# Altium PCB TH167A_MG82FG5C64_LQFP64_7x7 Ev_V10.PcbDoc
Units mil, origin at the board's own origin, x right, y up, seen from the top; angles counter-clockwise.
Board outline 3155 x 2110 mil, 2 copper layers (Top Layer, Bottom Layer); 56 components, 82 nets, 364 pads, 146 vias.
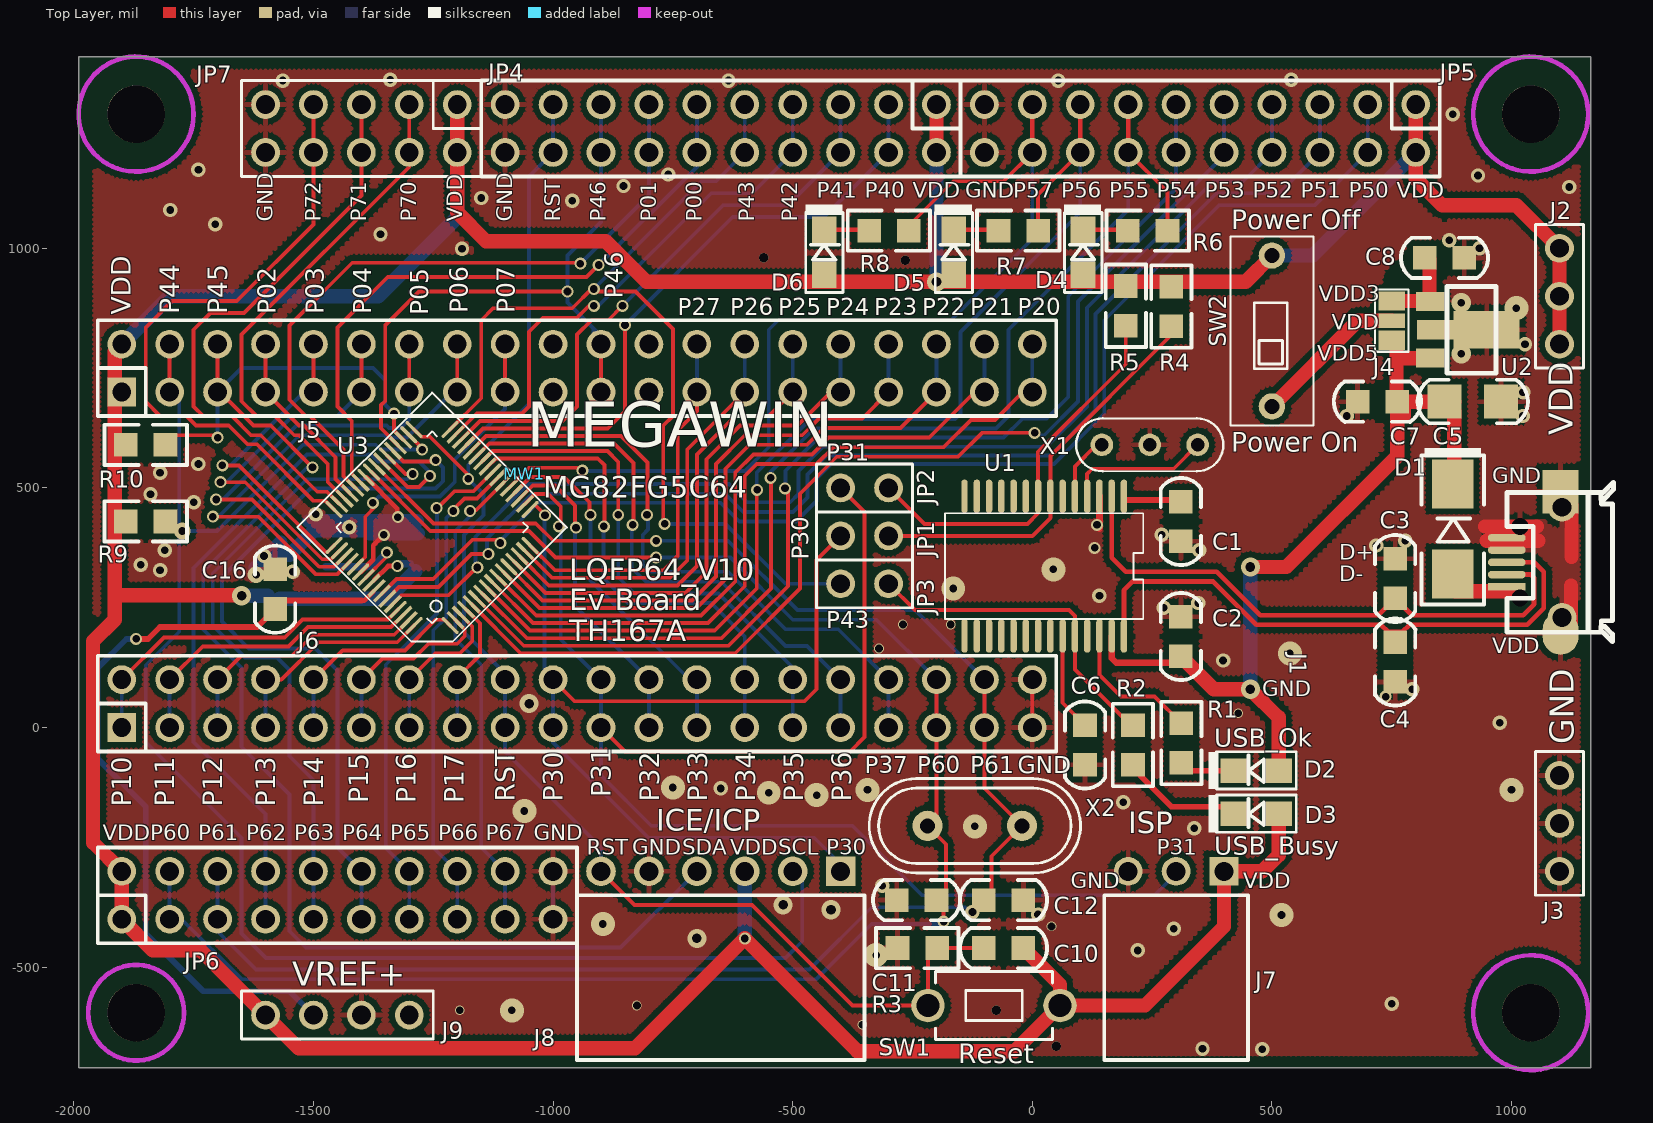
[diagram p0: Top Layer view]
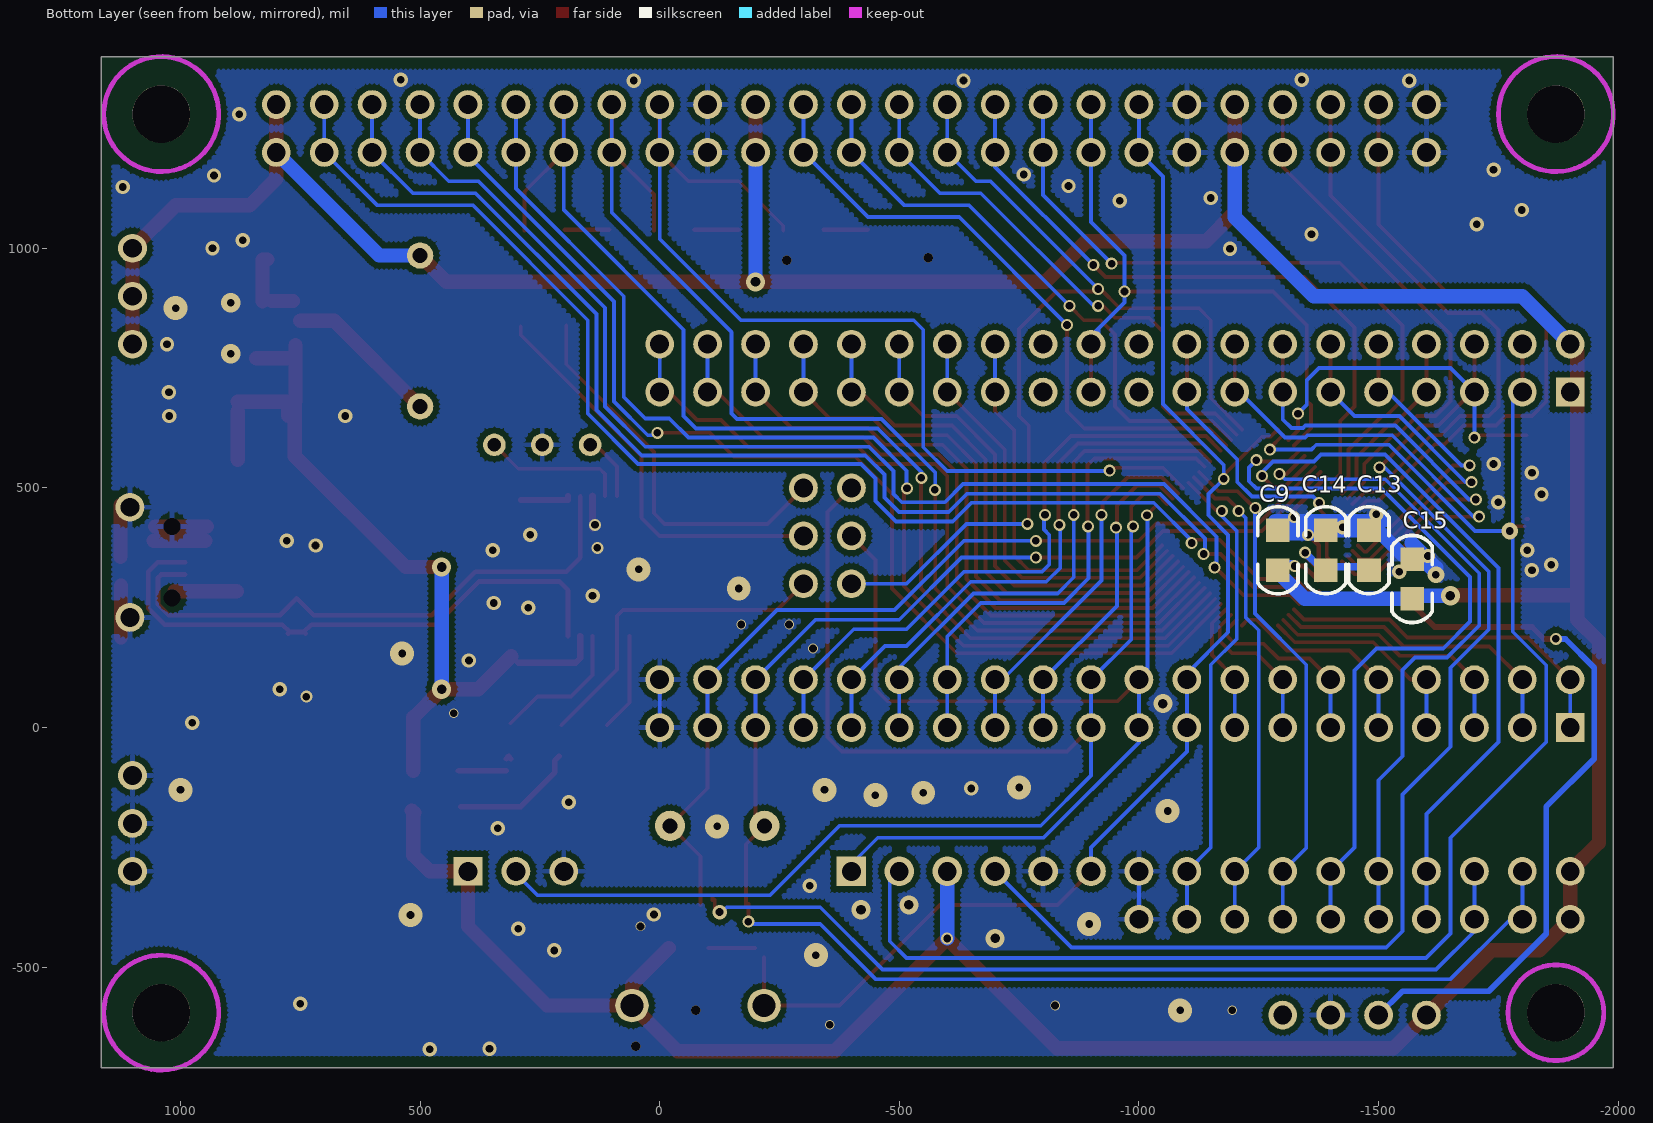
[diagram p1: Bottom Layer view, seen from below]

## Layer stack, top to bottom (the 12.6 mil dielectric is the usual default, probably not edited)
Top Layer: signal copper 1.4
Dielectric: dielectric 12.6, FR-4, Dk 4.8
Bottom Layer: signal copper 1.4

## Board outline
-1990,-710 -1990,1400 1165,1400 1165,-710

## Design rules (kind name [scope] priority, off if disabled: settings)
Clearance 12 [All] p1 off: gap=12
Clearance 10 [All] p2 off: gap=10
Clearance 6 [All] p3: gap=6
ComponentClearance [All] p1 off: gap=10 collisioncheckmode=3 verticalgap=10 showdistances=FALSE
HoleSize [All] p1: absolutevalues=TRUE maxlimit=500 minlimit=1 maxpercent=80.000 minpercent=20.000
MinimumSolderMaskSliver [All] p1 off: minsoldermaskwidth=10
PolygonConnect VIA [ISVIA] p1: connectstyle=Direct reliefconductorwidth=10 reliefentries=4 polygonreliefangle="90 Angle"
PolygonConnect [All] p2: connectstyle=Relief reliefconductorwidth=10 reliefentries=4 polygonreliefangle="90 Angle"
RoomDefinition TH167A_MG82FG5C64_LQFP64_V10 [InComponentClass('TH167A_MG82FG5C64_LQFP64_V10')] p1: confinementstyle=ConfineIn formatcopy=TRUE lockcomponents=FALSE outline -2265,-926 1350,-926 1350,1545 -2265,1545
RoutingVias [All] p1: holewidth=16 width=25 viastyle="Through Hole" minholewidth=16 minwidth=24 maxholewidth=28 maxwidth=50
SilkToSilkClearance [All] p1 off: silktosilkclearance=10
SilkscreenOverComponentPads [All] p1 off: minsilkscreentomaskgap=10
SolderMaskExpansion [All] p1 off: expansion=4
Width [All] p1: maxlimit=200 minlimit=6 preferedwidth=10
23 further rules are at their usual default settings.

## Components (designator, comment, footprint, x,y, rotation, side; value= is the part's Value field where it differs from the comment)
C1 "4.7uF" 0805C 310,430 r270 top
C2 "0.1uF" 0805C 310,190 r270 top
C3 "15pF" 0805C 757.2,310.79 r90 top
C4 "15pF" 0805C 757.2,136.62 r270 top
C5 "4.7uF" 1206C 919.06,680 r0 top
C6 "0.1uF" 0805C 110,-36.34 r90 top
C7 "0.1uF" 0805C 720,680 r180 top
C8 "4.7uF" 0805C 860,980 r0 top
C9 "0.1uF" 0805C -1290,370 r270 bottom
C10 "1u" 0805C -60,-460 r180 top
C11 "NC" 0805C -241.34,-360 r180 top
C12 "NC" 0805C -60,-360 r0 top
C13 "4.7uF" 0805C -1480,370 r90 bottom
C14 "0.1uF" 0805C -1390,370 r270 bottom
C15 "4.7uF" 0805C -1570,310 r90 bottom
C16 "0.1uF" 0805C -1580,288.66 r90 top
D1 "1N5817" D5817_SMD_1 877.2,414.45 r270 top
D2 "Yellow" 0805D 466.92,-90 r180 top
D3 "Red" 0805D 466.92,-180 r180 top
D4 "Green" 0805D 105.71,991.71 r90 top
D5 "Red" 0805D -164.29,991.71 r90 top
D6 "Green" 0805D -434.29,991.71 r90 top
J1 "Micro USB母座" JACK_USB_SMD290X220P065 990,344.72 r180 top
J2 "*" PS3P254 1100,800 r90 top
J3 "*" PS3P254 1100,-100 r270 top
J4 "*" JUMP3_SMD 750,849 r90 top
J5 "CON40A" PS20X2P254 -1900,700 r0 top locked
J6 "CON40A" PS20X2P254 -1900,0 r0 top
J7 "*" PS3P254f_90 400,-300 r180 top
J8 "*" PS6P254F_90 -400,-300 r180 top locked
J9 "CON4" PS4P254 -1600,-600 r0 top
JP1 "JUMPER2" PS2P254 -400,400 r0 top
JP2 "JUMPER2" PS2P254 -400,500 r0 top
JP3 "JUMPER2" PS2P254 -400,300 r0 top
JP4 "*" PS10X2P254 -200,1300 r180 top
JP5 "*" PS10X2P254 800,1300 r180 top
JP6 "*" PS10X2P254 -1900,-400 r0 top
JP7 "CON5X2" PS5X2P254 -1200,1300 r180 top
MW1 "MW-A4" MEGAWIN_T -1060,530 r0 top
R1 "1K" 0805R 311,-32.34 r270 top
R2 "1K" 0805R 210,-36.34 r270 top
R3 "47K" 0805R -240,-460 r0 top
R4 "4.7K" 0805R 290,878.66 r270 top
R5 "4.7K" 0805R 195,880 r270 top
R6 "1K" 0805R 240.71,1036.71 r180 top
R7 "1K" 0805R -29.29,1036.71 r180 top
R8 "1K" 0805R -299.29,1036.71 r180 top
R9 "4.7K" 0805R -1850,430 r180 top
R10 "4.7K" 0805R -1850,590 r180 top
SW1 "SW TACT-SPST" SW_T_2P -80,-580 r180 top
SW2 "-" DIP2_SW 500,670 r90 top
U1 "MA101_TSSOP28" SSOP28_220P065 24.84,336.85 r180 top
U2 "AIC1734-33(SOT-89)" SOT89 830,830 r270 top
U3 "MG82FG5C64" QFP64_7X7P040 -1252.42,417.62 r135 top locked (schematic designator U1)
X1 "6MHz" X3P 345,590 r180 top
X2 "NC" X49U -120,-205 r180 top

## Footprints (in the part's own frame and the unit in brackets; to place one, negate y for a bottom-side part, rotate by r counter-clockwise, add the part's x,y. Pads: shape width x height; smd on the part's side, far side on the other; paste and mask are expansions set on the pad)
0805C [mm]
  rect 1.25x1.25 smd: 1(-1.05,0) 2(1.05,0)
  silkscreen extent -2.31,-1.07 2.31,1.07
0805D [mm]
  rect 1.4x1.3 smd: 1(-1.192,0) 2(1.192,0)
  silkscreen extent -2.12,-1 2.53,0.98
0805R [mm]
  rect 1.25x1.25 smd: 1(-1.05,0) 2(1.05,0)
  silkscreen extent -2.18,-1.07 2.18,1.07
1206C [mm]
  rect 1.8x1.8 smd: 1(-1.5,0) 2(1.5,0)
  silkscreen extent -2.92,-1.15 2.92,1.16
D5817_SMD_1 [mm]
  rect 2.6x2.2 smd: 1(2.39,0) 2(-2.39,0)
  silkscreen extent -4.3,-1.65 4,1.65
DIP2_SW [mm]
  round 1.4 hole 0.8: 1(0,0) 2(8,0)
  silkscreen extent -1.02,-2.2 9.02,2.2
JACK_USB_SMD290X220P065 [mm]
  rect 1.9x1.8 on Mech2: 0(-2.85,-1.15) 0(-2.85,1.15)
  round 0.8 hole 0.9 unplated: 1(-0.7,1.9) 5(-0.7,-1.9)
  rect 2x0.4 smd: 1(0,1.3)
  oval 2x0.4 smd: 2(0,0.65) 3(0,0) 4(0,-0.65) 5(0,-1.3)
  round 1.524 hole 1: 5(-2.931,2.921) 5(-2.931,-2.921)
  oval 1.9x2.3 smd: 5(-2.85,3.75)
  rect 1.9x2.3 smd: 5(-2.85,-3.75)
  silkscreen extent -5.65,-4.25 -0.01,4.2
JUMP3_SMD [mil]
  rect 40x55 smd: 1(-41,0) 3(41,0)
  rect 30x55 smd: 2(0,0)
  silkscreen extent -65,-35 65,35
MEGAWIN_T [mil]
PS2P254 [mil]
  round 60 hole 39.37: 1(0,0) 2(100,0)
  silkscreen extent -50,-50 150,50
PS3P254 [mil]
  round 60 hole 39.37: 1(0,0) 2(100,0) 3(200,0)
  silkscreen extent -50,-50 250,50
PS3P254f_90 [mil]
  rect 60x60 hole 39.37: 1(0,0)
  round 60 hole 39.37: 2(100,0) 3(200,0)
  silkscreen extent -50,50 250,394
PS4P254 [mil]
  round 60 hole 39.37: 1(0,0) 2(100,0) 3(200,0) 4(300,0)
  silkscreen extent -50,-50 350,50
PS5X2P254 [mil]
  round 60 hole 39.37: 1(0,0) 2(0,100) 3(100,0) 4(100,100) 5(200,0) 6(200,100) 7(300,0) 8(300,100) 9(400,0) 10(400,100)
  silkscreen extent -50,-50 450,150
PS6P254F_90 [mil]
  rect 62x62 hole 39.37: 1(0,0)
  round 62 hole 39.37: 2(100,0) 3(200,0) 4(300,0) 5(400,0) 6(500,0)
  silkscreen extent -50,50 550,394
PS10X2P254 [mil]
  round 60 hole 39.37: 1(0,0) 2(0,100) 3(100,0) 4(100,100) 5(200,0) 6(200,100) 7(300,0) 8(300,100) 9(400,0) 10(400,100) 11(500,0) 12(500,100) 13(600,0) 14(600,100) 15(700,0) 16(700,100) 17(800,0) 18(800,100) 19(900,0) 20(900,100)
  silkscreen extent -50,-50 950,150
PS20X2P254 [mil]
  rect 60x60 hole 39.37: 1(0,0)
  round 60 hole 39.37: 2(0,100) 3(100,0) 4(100,100) 5(200,0) 6(200,100) 7(300,0) 8(300,100) 9(400,0) 10(400,100) 11(500,0) 12(500,100) 13(600,0) 14(600,100) 15(700,0) 16(700,100) 17(800,0) 18(800,100) 19(900,0) 20(900,100) 21(1000,0) 22(1000,100) 23(1100,0) 24(1100,100) 25(1200,0) 26(1200,100) 27(1300,0) 28(1300,100) 29(1400,0) 30(1400,100) 31(1500,0) 32(1500,100) 33(1600,0) 34(1600,100) 35(1700,0) 36(1700,100) 37(1800,0) 38(1800,100) 39(1900,0) 40(1900,100)
  silkscreen extent -50,-50 1950,150
QFP64_7X7P040 [mm]
  oval 1.2x0.19 smd: 1(-4.35,3) 12(-4.35,-1.4) 16(-4.35,-3) 33(4.35,-3) 34(4.35,-2.6) 38(4.35,-1) 41(4.35,0.2) 42(4.35,0.6) 48(4.35,3)
  rect 1.2x0.19 smd: 2(-4.35,2.6) 3(-4.35,2.2) 4(-4.35,1.8) 5(-4.35,1.4) 6(-4.35,1) 7(-4.35,0.6) 8(-4.35,0.2) 9(-4.35,-0.2) 10(-4.35,-0.6) 11(-4.35,-1) 13(-4.35,-1.8) 14(-4.35,-2.2) 15(-4.35,-2.6) 35(4.35,-2.2) 36(4.35,-1.8) 37(4.35,-1.4) 39(4.35,-0.6) 40(4.35,-0.2) 43(4.35,1) 44(4.35,1.4) 45(4.35,1.8) 46(4.35,2.2) 47(4.35,2.6)
  oval 0.19x1.2 smd: 17(-3,-4.35) 24(-0.2,-4.35) 27(1,-4.35) 32(3,-4.35) 49(3,4.35) 50(2.6,4.35) 53(1.4,4.35) 54(1,4.35) 61(-1.8,4.35) 64(-3,4.35)
  rect 0.19x1.2 smd: 18(-2.6,-4.35) 19(-2.2,-4.35) 20(-1.8,-4.35) 21(-1.4,-4.35) 22(-1,-4.35) 23(-0.6,-4.35) 25(0.2,-4.35) 26(0.6,-4.35) 28(1.4,-4.35) 29(1.8,-4.35) 30(2.2,-4.35) 31(2.6,-4.35) 51(2.2,4.35) 52(1.8,4.35) 55(0.6,4.35) 56(0.2,4.35) 57(-0.2,4.35) 58(-0.6,4.35) 59(-1,4.35) 60(-1.4,4.35) 62(-2.2,4.35) 63(-2.6,4.35)
  silkscreen extent -5.05,-5.05 5.05,5.05
SOT89 [mm]
  rect 1.016x1.5 smd: 1(-1.5,0) 3(1.5,0)
  rect 2x3.5 smd: 2(0,3)
  rect 1.016x2.6 smd: 2(0,0.6)
  silkscreen extent -2.3,0.9 2.3,3.5
SSOP28_220P065 [mil]
  oval 13.5x70 smd: 1(-166.34,-145.67) 2(-140.75,-145.67) 3(-115.16,-145.67) 4(-89.57,-145.67) 5(-63.98,-145.67) 6(-38.39,-145.67) 7(-12.79,-145.67) 8(12.8,-145.67) 9(38.39,-145.67) 10(63.98,-145.67) 11(89.57,-145.67) 12(115.16,-145.67) 13(140.75,-145.67) 14(166.34,-145.67) 15(166.34,145.67) 16(140.75,145.67) 17(115.16,145.67) 18(89.57,145.67) 19(63.98,145.67) 20(38.39,145.67) 21(12.8,145.67) 22(-12.79,145.67) 23(-38.39,145.67) 24(-63.98,145.67) 25(-89.57,145.67) 26(-115.16,145.67) 27(-140.75,145.67) 28(-166.34,145.67)
  silkscreen extent -207,-110 207,110
SW_T_2P [mil]
  round 70 hole 47.24: 1(-137.79,0) 2(137.79,0)
  silkscreen extent -122,-71 122,71
X3P [mm]
  round 1.2 hole 0.711: 1(0,0) 2(5.08,0) 3(2.54,0)
  silkscreen extent -1.36,-1.4 6.44,1.4
X49U [mm]
  round 1.6 hole 0.8: 1(-2.5,0) 2(2.5,0)
  silkscreen extent -5.6,-2.5 5.6,2.5

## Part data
C1 C5 C8 C13 C15: library part CAP
C2 C3 C4 C6 C7 C9 C14 C16: library part "CAP NP"
C10: library part C
C11 C12: library part "C NP"
D1: library part DIODE_ZD, "Schottky Diode"
D2 D3 D4 D5 D6: library part LED
J1: library part CON5, "Connector"
J2 J3 J4 J7: library part CON3
J8: library part CON6
JP4 JP5 JP6: library part CON10X2
R1 R2 R4 R5 R6 R7 R8: library part R_Dup1
R3 R9 R10: library part R
SW2: library part SW-2
U2: library part AIC1734-33(SOT-89)_0
U3: library part MG82FG5C64_LQFP64
X1: library part CRYSTAL_RC
X2: library part CRYSTAL

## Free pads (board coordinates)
  round 120 hole 120 unplated: 0(-1870,-595) 0(-1870,1280) 0(1040,-595) 0(1040,1280)

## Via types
v1: diameter 30, hole 16, Top Layer to Bottom Layer, tented both sides, 55 vias
v2: diameter 25, hole 16, Top Layer to Bottom Layer, tented both sides, 52 vias
v3: diameter 50, hole 16, Top Layer to Bottom Layer, tented both sides, 15 vias
v4: diameter 20, hole 16, Top Layer to Bottom Layer, tented both sides, 8 vias
v5: diameter 40, hole 20, Top Layer to Bottom Layer, tented both sides, 8 vias
v6: diameter 20, hole 20, Top Layer to Bottom Layer, tented both sides, 4 vias
v7: diameter 35, hole 16, Top Layer to Bottom Layer, tented both sides, 2 vias
v8: diameter 40, hole 16, Top Layer to Bottom Layer, tented both sides, 2 vias

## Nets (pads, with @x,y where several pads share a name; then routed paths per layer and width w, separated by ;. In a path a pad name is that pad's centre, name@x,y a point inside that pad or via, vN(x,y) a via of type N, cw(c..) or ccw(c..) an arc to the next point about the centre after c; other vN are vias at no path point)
D+: C4.1 J1.3 U1.28 | length 1213
  Top Layer w10: U1.28 191.18,286.18 210,305 376.72,305 467.27,214.45 727.2,214.45 C4.1@742.2,199.45 ; C4.1@738.96,196.21 C4.1@742.2,199.45 ; C4.1@775.45,196.21 C4.1@772.2,199.45 ; J1.3 1046.93,344.72 1067,324.65 1067,249 1032.45,214.45 787.2,214.45 C4.1@772.2,199.45 ; C4.1@742.2,199.45 757.2,199.45 C4.1@772.2,199.45
D-: C3.1 J1.2 U1.2 | length 1212.7
  Top Layer w10: U1.2 165.59,354.41 195,325 385,325 475.55,234.45 722.2,234.45 C3.1 792.2,234.45 1024.16,234.45 1047,257.28 1047,312.57 1040.43,319.13 J1.2
GND_POWER: C1.2 C2.1 C3.2 C4.2 C5.2 C6.1 C7.2 C8.2 C9.1 C11.2 C12.2 C13.2 C14.1 C15.2 C16.2 J1.4 J1.5 J3.1 J3.2 J3.3 J6.39 J6.40 J7.3 J8.5 J9.3 JP4.19 JP4.20 JP5.19 JP5.20 JP6.19 JP6.20 JP7.9 JP7.10 R3.1 U1.3 U2.2 U3.42 U3.54 X1.3 | length 1666.2
  Top Layer w8: J6.39 J6.40
  Top Layer w10: U3.54 -1375,350.71 -1375,380 v2(-1353,402) ; U3.42 -1325,456.79 -1325,439 v2@-1325,436
  Top Layer w15: v2@140,416 140,423 U1.3
  Top Layer w30: 944.48,419.53 1017.56,419.53 1052.28,419.53 ; 948.2,390 990,390 1017.56,390 1056,390 ; J1.5@1124,188 1124,197.09 1124,229.72 1124,295.8 ; 1125,356.2 1125,459.72 J1.5@1125,464
  Bottom Layer w8: JP6.19 JP6.20 ; J6.39 J6.40
  Bottom Layer w10: C14.1@-1379,405.01 -1379,411.34 C14.1@-1379,425.68
  Bottom Layer w30: v7@-1620,334 -1599.5,354.5 -1586.33,367.67 -1568.66,385.34 ; v7@-1615.33,327.67 -1601,342 ; v1@-1597.66,345.34 -1601,342 ; C15.2@-1587,342 -1601,342 ; C15.2@-1570,360 -1550,360 -1498.66,411.34 C13.2 -1425,411.34 C14.1 ; -1509,431 -1495,431 -1480,431 -1425,431 -1390,431 -1324,431 -1290,431 C9.1@-1284.69,431 ; C14.1@-1382,405.01 -1379,405.01 -1353,405.01 -1290,405.01 C9.1@-1282,405.01
  other v1: 480,-671 355,-670 750,-576 220,-465 295,-420 12,-390 -313,-330 338,-210 190,-156 -650,-127 975,10 793,80 398,140 274,250 346,260 140,275 -1543,325 -1820,328 -1860,340 -1603,358 -1810,370 348,370 718,380 778,390 270,402 -1425,418 -1495,445 -1750,470 -1840,487 -1820,532 -1740,550 656,650 1023,650 1024,700 1028,800 -1190,999 933,1000 870,1017 -1360,1029 -1705,1050 -1799,1080 -960,1099 -1150,1105 1120,1128 -853,1130 930,1152 -760,1154 -1740,1164 877,1280 -1564,1350 -634,1350 54,1350 -1340,1352 540,1352
  other v2: 737.2,64.45 130,375 135,423 -1324,439
  other v3: -1086,-590 -326,-475 -896,-410 520,-391 -120,-206 -1060,-174 -450,-141 -550,-136 -344,-130 1000,-130 -750,-125 537.2,154.45 -165,290 44,330 1010,875
  other v4: -355,-620 -1195,-590 -825,-580 40,-415 430,30 -320,165 -270,215 -170,215
  other v5: -700,-440 -420,-380 -520,-370 -1050,50
  other v6: 50,-665 -75,-590 -265,975 -560,980
  other v7: -1619.61,319
  other v8: 895,780 895,886.37
MA101_RX: JP2.2 R5.2 U1.8 | length 819.6
  Top Layer w8: JP2.2 -225,425 -10,425 12.05,447.05 U1.8 12.05,575.04 195,757.99 R5.2
MA101_TX: JP1.2 R4.2 U1.7 | length 857.4
  Top Layer w8: JP1.2 0,400 37.64,437.64 U1.7 37.64,566.64 290,819 R4.2
NetC1_1: C1.1 U1.1 | length 105
  Top Layer w13: U1.1 191.18,475 C1.1@288.66,475
NetC6_2: C6.2 U1.23 | length 205.6
  Top Layer w8: U1.23 63.23,51.77 C6.2
NetC13_1: C13.1 C14.2 U3.55 | length 202.2
  Top Layer w8: U3.55 -1347,356.44 v2(-1347,365)
  Bottom Layer w8: C14.2@-1390,335.5 C14.2@-1386.33,335.5
  Bottom Layer w15: C13.1@-1475,335.5 C14.2@-1390,335.5 ; C14.2@-1378,334 v2(-1347,365)
NetD1_1: D1.1 J1.1 | length 130
  Top Layer w30: D1.1@882.2,284.45 990,284.45 J1.1@1012.2,284.45
NetD2_2: D2.2 R1.2 | length 107.2
  Top Layer w12: R1.2@310.6,-65 R1.2@311,-65 ; R1.2@315,-60 R1.2@319.84,-64.84 ; R1.2@320,-90 D2.2
NetD3_2: D3.2 R2.2 | length 263.1
  Top Layer w12: R2.2@210,-60 218.84,-68.84 218.84,-77.68 218.84,-93.84 290,-165 D3.2@415,-165
NetD4_2: D4.2 R6.2 | length 91.7
  Top Layer w10: D4.2 R6.2@197.45,1038.63
NetD5_2: D5.2 R7.2 | length 91.7
  Top Layer w10: D5.2 R7.2@-72.55,1038.63
NetD6_2: D6.2 R8.2 | length 91.7
  Top Layer w10: D6.2 R8.2@-342.55,1038.63
NetJ4_2: J4.2 SW2.1 | length 324.1
  Top Layer w30: SW2.1 679,849 J4.2
NetU1_4: U1.4 X1.1 | length 302.6
  Top Layer w8: U1.4 114.41,529.41 125,540 295,540 X1.1
NetU1_5: U1.5 X1.2 | length 137.3
  Top Layer w8: U1.5 88.82,545 133.82,590 X1.2
P00: JP4.11 JP4.12 U3.43 | length 1363
  Top Layer w8: U3.43 -1420,529.52 -1420,640 -1450,670 -1450,835 -1345,940 -930,940 v2(-905,965)
  Bottom Layer w8: v2(-905,965) -700,1170 JP4.12 JP4.11
P01: JP4.13 JP4.14 U3.44 | length 1451
  Top Layer w8: U3.44 -1437,524.25 -1437,580 -1507,650 -1516,650 -1550,684 -1550,839 -1419,970 v2@-950,970
  Bottom Layer w8: v2@-943,972 v2(-943,968) -800,1111 JP4.14 JP4.13
P02: J5.7 J5.8 U3.45 | length 410.3
  Top Layer w8: J5.8 J5.7 -1530,630 -1520,630 -1454,564 -1454,518.98 U3.45
  Bottom Layer w8: J5.7@-1620,700 J5.7
P03: J5.9 J5.10 U3.49 | length 667.3
  Top Layer w8: v2(-1690,547) -1655,547 -1474.99,366.99 -1470.07,366.99 U3.49 ; J5.9 J5.10
  Bottom Layer w8: v2(-1690,547) -1673,547 -1520,700 J5.9@-1524,700 ; J5.9@-1517,700 J5.9
P04: J5.11 J5.12 U3.50 | length 799.4
  Top Layer w8: v2(-1694,512) -1642.27,512 -1481.52,351.24 -1463.55,351.24 U3.50 ; J5.11 J5.12
  Bottom Layer w8: v2@-1694,508 v2@-1688.48,508 ; v2(-1694,512) -1681.48,512 -1543.48,650 -1450,650 J5.11
P05: J5.13 J5.14 U3.51 | length 969
  Top Layer w8: v2(-1703,476) -1628.54,476 -1488.04,335.5 -1457.03,335.5 U3.51 ; J5.13 J5.14
  Bottom Layer w8: v2(-1703,476) -1689,476 -1535,630 -1347,630 -1342,625 -1318,625 -1300,643 J5.13
P06: J5.15 J5.16 U3.52 | length 1077.7
  Top Layer w8: v2(-1710,440) -1614.81,440 -1494.56,319.75 -1450.5,319.75 U3.52 ; J5.15 J5.16
  Bottom Layer w8: v2@-1701.44,440 v2(-1710,440) -1698.44,440 -1528.44,610 -1352,610 -1347,605 -1305,605 -1210,700 J5.15
P07: J5.17 J5.18 U3.53 | length 664.7
  Top Layer w8: U3.53 -1392,355.98 -1392,440 -1370,462 v2@-1373,462 ; J5.17@-1100,717.01 J5.18
  Bottom Layer w8: v2(-1376,469) -1363,482 -1236,482 -1205,513 -1205,560 -1100,665 J5.17 ; v2@-1373,462 v2@-1371,464 ; J5.17@-1108.51,708.51 J5.17@-1100,717.01
P10: J6.1 J6.2 U3.61 | length 737.2
  Top Layer w8: J6.2 -1811.99,188.01 -1559.99,188.01 -1522.76,225.24 -1344.57,225.24 U3.61
  Bottom Layer w8: J6.1 J6.2
P11: J6.3 J6.4 U3.62 | length 643.8
  Top Layer w8: J6.4 -1730.99,169.01 -1551.99,169.01 -1511.5,209.5 -1338.05,209.5 U3.62
  Bottom Layer w8: J6.3 J6.4
P12: J6.5 J6.6 U3.63 | length 550.3
  Top Layer w8: J6.6 -1650,150 -1544,150 -1500.25,193.75 -1331.52,193.75 U3.63
  Bottom Layer w8: J6.5 J6.6
P13: J6.7 J6.8 U3.64 | length 534.5
  Top Layer w8: J6.8@-1572.27,100 J6.8 -1567.01,100 -1489.01,178 -1365,178 ; -1415,178 -1365,178 ; U3.64 -1325,178 -1365,178
  Bottom Layer w8: J6.7 J6.8
P14: J6.9 J6.10 U3.1 | length 441.9
  Top Layer w8: J6.10 -1439,161 -1309,161 -1245,225 -1226.84,225 U3.1
  Bottom Layer w8: J6.9 J6.10
P15: J6.11 J6.12 U3.2 | length 423.1
  Top Layer w8: J6.12@-1380,120 J6.12 -1356,144 -1291,144 -1260,175 -1200,175 -1184.25,190.75 -1184.25,204.69 U3.2
  Bottom Layer w8: J6.11 J6.12
P16: J6.13 J6.14 U3.3 | length 329.9
  Top Layer w8: J6.14@-1300.29,100 J6.14 -1245,155 -1194,155 -1168.5,180.5 -1168.5,211.21 U3.3
  Bottom Layer w8: J6.13 J6.14
P17: J6.15 J6.16 U3.4 | length 324.3
  Top Layer w8: J6.16 -1200,104 -1152.76,151.24 -1152.76,217.73 ; U3.4 -1152.76,217.73 ; -1152.76,171.24 -1152.76,217.73
  Bottom Layer w8: J6.15 J6.16
P20: J5.39 J5.40 U3.9 | length 1595
  Top Layer w8: U3.9 -1041.67,218.01 -676.99,218.01 -600,295 -600,525 -575,550 -450,550 -415,585 -185,585 -128,642 -78,642 -20,700 J5.39
  Bottom Layer w8: J5.39 J5.40
P21: J5.37 J5.38 U3.10 | length 1473.6
  Top Layer w8: U3.10 -1035.15,233.76 -691.24,233.76 -620,305 -620,532.01 -582.01,570 -460,570 -425,605 -215,605 -120,700 J5.37
  Bottom Layer w8: J5.37 J5.38
P22: J5.35 J5.36 U3.11 | length 1355.8
  Top Layer w8: U3.11 -1028.63,249.5 -700.5,249.5 -640,310 -640,540 -590,590 -470,590 -435,625 -275,625 J5.35
  Bottom Layer w8: J5.35 J5.36
P23: J5.33 J5.34 U3.12 | length 1239.2
  Top Layer w8: U3.12 -1022.11,265.25 -709.75,265.25 -660,315 -660,550 -600,610 -480,610 -445,645 -355,645 J5.33
  Bottom Layer w8: J5.33 J5.34
P24: J5.31 J5.32 U3.13 | length 1119.6
  Top Layer w8: U3.13 -1015.58,281 -724,281 -680,325 -680,560 -610,630 -490,630 -420,700 J5.31
  Bottom Layer w8: J5.31 J5.32
P25: J5.29 J5.30 U3.14 | length 1001
  Top Layer w8: U3.14 -1009.06,296.75 -740,296.75 -700,336.75 -700,570 -620,650 -550,650 J5.29 J5.29@-500,702.01
  Bottom Layer w8: J5.29 J5.30
P26: J5.27 J5.28 U3.15 | length 878.5
  Top Layer w8: U3.15 -1002.54,312.5 -755.85,312.5 -720,348.35 -720,580 J5.27
  Bottom Layer w8: J5.27 J5.28
P27: J5.25 J5.26 U3.16 | length 800
  Top Layer w8: U3.16 -996.01,328.24 -770,328.24 -740,358.24 -740,620 -700,660 J5.25
  Bottom Layer w8: J5.25 J5.26
P30/RXD: J6.19 J6.20 J8.1 JP1.1 U3.17 | length 2139.3
  Top Layer w8: U3.17@-1036,463 v2@-1020.24,447.24 ; v2@-1018,442 v2@-1018,443 ; J6.20 -955,55 -475,55 -450,80 -450,350 JP1.1
  Bottom Layer w8: v2@-1018,442 -1018,118 J6.20 J6.19 -1000,-31 -801,-230 -455,-230 J8.1@-392.5,-292.5
  other v2: -1017,443
P31/TXD: J6.21 J6.22 J7.2 JP2.1 U3.18 | length 3250.9
  Top Layer w8: U3.18 -1038.27,487 -1010,487 -984,461 -984,424 v2(-988,420) ; J6.21 -850,-50 -380,-50 -350,-20 -350,450 JP2.1
  Bottom Layer w8: v2@-984,420 -984,184 J6.22 ; -980,180 J6.22 ; J7.2@300,-305 255,-350 -230,-350 -375,-205 -795,-205 -900,-100 J6.21 J6.22
P32: J6.23 J6.24 U3.19 | length 678.7
  Top Layer w8: U3.19 -1042.54,505 -996,505 -954,463 v2@-954,417
  Bottom Layer w8: v2@-954,424 -954,417 -954,254 J6.24 J6.23
  other v2: -952,417
P33: J6.25 J6.26 U3.20 | length 746
  Top Layer w8: U3.20 -1046.81,523 -977,523 -924,470 v2@-924,455
  Bottom Layer w8: v2@-926,444 -924,442 -922,440 -922,307 -707.5,92.5 -700,85 J6.25
  other v2: -922,444
P34: J6.27 J6.28 U3.25 | length 1032.6
  Top Layer w8: U3.25 -1119.41,561.76 -906.76,561.76 -893,548 v2@-893,420
  Bottom Layer w8: v2@-895,424 -895,420 -895,311.5 -843.5,260 -670,260 -600,190 J6.28 J6.27
  other v2: -894,420
P35: J6.29 J6.30 U3.26 | length 1109.9
  Top Layer w8: U3.26 -1126.68,576.76 -886.76,576.76 -864,554 v2(-864,444)
  Bottom Layer w8: v2(-864,444) -864,313.51 -830.49,280 -655,280 -500,125 J6.30 J6.29
P36: J6.31 J6.32 U3.27 | length 1205.9
  Top Layer w8: U3.27 -1133.21,592.5 -872.5,592.5 -832,552 v2@-832,424
  Bottom Layer w8: v2@-836,424 -836,423 -836,333.5 -806.68,304.17 -649.17,304.17 -515,170 -470,170 J6.32 J6.31
  other v2: -834,423
P37: J6.33 J6.34 U3.28 | length 1335.3
  Top Layer w8: U3.28 -1139.73,608.25 -858.25,608.25 -803,553 v2@-803,444
  Bottom Layer w8: v2(-804,444) v2@-802,442 ; v2@-802,444 v2@-802,442 ; J6.33 J6.34 -405,205 -515,205 -635,325 -797.5,325 -813,340.5 -813,402 -802,413 v2@-802,442
P40: JP4.3 JP4.4 U3.29 | length 1340
  Top Layer w8: U3.29 -1146.25,624 -886,624 -850,660 v2(-850,840)
  Bottom Layer w8: v2(-850,840) -625,1065 -435,1065 JP4.4 JP4.3
P41: JP4.5 JP4.6 U3.30 | length 1229
  Top Layer w8: U3.30 -1152.78,639.75 -980.25,639.75 -950,670 -950,820 -920,850 -885,850 v2(-855,880)
  Bottom Layer w8: v2(-855,880) -645,1090 -510,1090 JP4.6 JP4.5
P42: JP4.7 JP4.8 U3.31 | length 1139
  Top Layer w8: U3.31 -1159.3,655.5 -1064.5,655.5 -1050,670 -1050,826 -1021,855 -950,855 -925,880 v2(-915,880)
  Bottom Layer w8: v2(-915,880) -905,880 -670,1115 -585,1115 JP4.8 JP4.7
P43: JP3.1 JP4.9 JP4.10 U3.32 | length 2087.2
  Top Layer w8: U3.32 -1150,687.07 -1150,850 -1125,875 -960,875 -917.5,917.5 -915,920 -912.5,917.5 -905,910 -828,910 -750,832 -750,650 -770,630 v2@-770,425
  Bottom Layer w8: v2(-915,915) -690,1140 -660,1140 JP4.10 JP4.9 ; v2(-767,425) -640,425 -515,300 JP3.1
P44: J5.3 J5.4 J8.2 R9.1 U3.34 | length 3488
  Top Layer w8: R9.1@-1812.32,435 R9.1@-1808.66,435 ; R9.1@-1805,420 -1773.66,420 v7@-1770,420 ; J5.3@-1800,675 J5.3 J5.4 ; U3.34 v2@-1271.52,581.48
  Bottom Layer w8: J5.3 -1780,680 v7@-1780,410 ; v2(-1273,580) -1360,580 -1370,590 -1521.48,590 -1701.48,410 v7(-1773.66,410) v7@-1780,410 ; -480,-440 -480,-350 ; J8.2@-480,-295 -480,-300 -480,-350 ; v7@-1780,410 -1780,200 -1850,130 -1850,-30 -1650,-230 -1650,-430 -1599,-481 -515,-481 -480,-446 -480,-350
P45: J5.5 J5.6 J8.4 R10.1 U3.35 | length 3158
  Top Layer w8: R10.1@-1808.66,610 v2@-1700,610 ; J5.6 J5.5 -1695,700 -1625,630 -1589,630 v2(-1502,543) ; v2(-1332,655) -1332,619.69 U3.35
  Bottom Layer w8: v2(-1700,605) J5.5 -1650,750 -1376,750 -1350,724 -1350,673 v2(-1332,655) ; v2@-1507.5,548.5 -1730,326 -1730,204.85 -1650,124.85 -1650,-40 -1550,-140 -1550,-425 -1516,-459 -859,-459 J8.4
P46: J5.21 J5.22 JP4.15 JP4.16 U3.36 | length 1352.6
  Top Layer w8: U3.36 -1359,624.42 -1359,673.01 -1350,682.01 -1350,840 -1280,910 -1010,910 ; -997,910 -1010,910 ; v2(-970,910) -1010,910 ; J5.21 J5.22
  Bottom Layer w8: J5.22@-915.6,815.6 -915.6,832.6 ; JP4.16@-913,1200 JP4.16@-913,1203 ; J5.22@-900,817 -915.6,832.6 ; JP4.15 JP4.16 -900,1055 -970,985 v2(-970,910) -970,887 -915.6,832.6
P50: JP5.3 JP5.4 U3.58 | length 2720.8
  Top Layer w8: U3.58 -1326.63,310 -1250,310 -1167.99,392.01 -1117.01,392.01 v2(-1110,385)
  Bottom Layer w8: v2(-1110,385) -1110,390 -1031,469 -650.57,469 -611.57,430 -493,430 -450,473 -450,520 -420,550 45,550 150,655 150,850 390,1090 590,1090 JP5.4 JP5.3
P51: JP5.5 JP5.6 U3.59 | length 2633.3
  Top Layer w8: U3.59 -1321.36,293 -1239,293 -1170,362 v2(-1135,362)
  Bottom Layer w8: v2(-1135,362) -1133,364 -1138,369 -1138,394.26 -1044.26,488 -641.28,488 -603.28,450 -499,450 -469,480 -469,528 -429,568 37.54,568 132,662.46 132,863 384,1115 515,1115 JP5.6 JP5.5
P52: JP5.7 JP5.8 U3.60 | length 2548.9
  Top Layer w8: U3.60 -1316.08,276 -1218,276 -1159,335 v2@-1156,338
  Bottom Layer w8: v2@-1156,338 -1162,344 -1162,398 -1052,508 -633,508 -595,470 -505,470 -488,487 -488,535 -437,586 30.09,586 114,669.91 114,876 378,1140 440,1140 JP5.8 JP5.7
  other v2: -1158,334
P53: JP5.9 JP5.10 U3.5 | length 2392.9
  Top Layer w8: U3.5 -1067.75,155 -620,155 -485,290 -485,488 -408,565 -155,565 -105,615 v2(5,615)
  Bottom Layer w8: v2@0,610 5,610 25,610 95,680 95,889 JP5.10@403,1197 ; JP5.10 JP5.9
P54: JP5.11 JP5.12 U3.6 | length 2334.1
  Top Layer w8: U3.6 -1061.23,170.75 -634.25,170.75 -510,295 -510,499 -510,500 -512.5,502.5 v2@-513.5,503.5
  Bottom Layer w8: v2@-515,510 -515,536 -446,605 -60,605 -20,645 30,645 75,690 75,900 300,1125 JP5.12 JP5.11
  other v2: -516,499
P55: JP5.13 JP5.14 R6.1 U3.7 | length 2555.4
  Top Layer w8: U3.7 -1054.7,186.5 -648.5,186.5 -545,290 v2@-545,521 ; JP5.14 282.05,1117.95 R6.1 ; JP5.13 JP5.13@218.66,1281.34
  Top Layer w10: JP5.14@195.67,1204.33 JP5.14@200,1208.66 ; JP5.14 JP5.14@200,1208.66 ; JP5.13 JP5.14@200,1208.66
  Bottom Layer w8: v2(-546,521) -546,533 -455,624 -76,624 -50,650 -50,830 200,1080 JP5.14 JP5.13
P56: JP5.15 JP5.16 R7.1 U3.8 | length 2395.2
  Top Layer w8: U3.8 -1048.18,202.24 -662.76,202.24 -575,290 v2@-575,490 ; R7.1 12.05,1112.05 JP5.16
  Top Layer w10: JP5.16 JP5.15
  Bottom Layer w8: v2@-575,496 -575,532 -463,644 -161,644 -150,655 -150,825 100,1075 JP5.16 JP5.15
  other v2: -574,496
P57: JP5.17 JP5.18 R8.1 U3.21 | length 2175.6
  Top Layer w8: U3.21 -1050.08,542 -947.5,542 -940.5,535 -939.25,536.25 -935,540.5 v2@-934.49,540.5 ; R8.1 -257.95,1047.05 -165,1140 -60,1140 JP5.18
  Top Layer w10: JP5.18 JP5.17
  Bottom Layer w8: v2@-939,535 -600,535 -550,585 -550,830 -530,850 -170,850 0,1020 JP5.18 JP5.17
  other v2: -939,536
P60: C11.1 J6.35 J6.36 JP6.3 JP6.4 U3.41 X2.2 | length 3808.5
  Top Layer w8: U3.41 -1256.2,410.26 -1050.26,410.26 -994.74,354.74 v2(-785,354.74) ; J6.36 J6.35 -200,-186.58 X2.2 -180,-243.42 -180,-360 C11.1@-180,-370 ; v2@-185,-410 v2(-185,-405) C11.1@-185,-368
  Bottom Layer w8: JP6.4 JP6.3 -1775,-400 -1650,-525 -450,-525 -335,-410 v2@-185,-410 ; v2(-785,354.74) -629.59,354.74 -499.85,225 -325,225 J6.36 J6.35
P61: C12.1 J6.37 J6.38 JP6.5 JP6.6 U3.40 X2.1 | length 3902.4
  Top Layer w8: U3.40 -1249.68,426.01 -1036.01,426.01 -999.74,389.74 v2(-785,389.74) ; v1@-115,-385 C12.1@-115,-360 ; C12.1@-110,-360 C12.1@-110,-353 ; J6.38 J6.37 -100,-126.58 X2.1 -85,-268.42 -85,-360 C12.1@-85,-370
  Bottom Layer w8: JP6.6 JP6.5 -1700,-425 -1620,-505 -465,-505 -335,-375 -140,-375 v1@-127.5,-387.5 ; v2(-785,389.74) -634.74,389.74 -490,245 -245,245 J6.38 J6.37
  other v1: -125,-385
P62: JP6.7 JP6.8 U3.39 | length 1576
  Top Layer w8: -1332.47,531.08 U3.39 -1303.41,502.01 -1279.99,502.01 -1261,521 v2@-1261,525
  Bottom Layer w8: JP6.7 JP6.8 -1600,-180 -1750,-30 -1750,333.3 -1513.3,570 -1380,570 -1365,555 -1279.82,555 -1257.83,533.01 -1257,533.01 -1255,533.01 v2@-1255,525
  other v2: -1257,525
P63: JP6.9 JP6.10 U3.38 | length 1446.5
  Top Layer w8: U3.38 -1308.12,529 v2(-1293,529) v2@-1292,529
  Bottom Layer w8: JP6.9@-1500,-425 JP6.9 JP6.10 -1500,-110 -1550,-60 -1550,120 -1576,146 -1642.87,146 -1710,213.13 -1710,322 -1514,518 -1305,518 -1293.5,529.5 v2@-1293,530 ; v2(-1293,529) v2@-1292,529
P64: JP6.11 JP6.12 U3.37 | length 1610.3
  Top Layer w8: U3.37 -1311.85,555 -1248,555 v2(-1245,558)
  Bottom Layer w8: JP6.11 JP6.12 -1450,-250 -1450,119 -1496,165 -1635,165 -1691,221 -1691,314.13 -1506.13,499 -1245,499 -1230,514 -1230,543 v2(-1245,558)
P65: JP6.13 JP6.14 U3.24 | length 1070.9
  Top Layer w8: v2(-1243,458) -1241,458 -1206,493 -1165.9,493 U3.24
  Bottom Layer w8: JP6.13 JP6.14 -1349,-251 -1349,131 -1242.29,237.71 v2@-1242.29,458
P66: JP6.15 JP6.16 U3.23 | length 1013.4
  Top Layer w8: v2@-1209.5,453.5 -1185,478 -1158.63,478 U3.23
  Bottom Layer w8: v2(-1208,452) -1223,437 -1223,230 -1250,203 -1250,-250 JP6.16 JP6.15
P67: JP6.17 JP6.18 U3.22 | length 1001
  Top Layer w8: v2@-1173,454 -1160.36,454 U3.22
  Bottom Layer w8: v2(-1173,452) -1173,441 -1204,410 -1204,185 -1150,131 -1150,-250 JP6.18 JP6.17
P70: JP7.3 JP7.4 U3.46 | length 1085.4
  Top Layer w8: U3.46 -1470,512.71 -1470,550 -1530,610 -1540,610 -1580,650 -1619,650 -1650,681 -1650,820 -1300,1170 JP7.4 JP7.3
P71: JP7.5 JP7.6 U3.47 | length 1204.4
  Top Layer w8: U3.47 -1471.56,492 -1492,492 -1610,610 -1630,610 -1670,650 -1730,650 -1750,670 -1750,830 -1715,865 -1645,865 -1400,1110 JP7.6 JP7.5
P72: JP7.7 JP7.8 U3.48 | length 1330.1
  Top Layer w8: JP7.7 JP7.8 -1500,1050 -1660,890 -1795,890 -1850,835 -1850,680 -1820,650 -1765,650 -1745,630 -1676.71,630 -1637.82,591.11 -1617.82,591.11 -1499.82,473.11 -1474.95,473.11 U3.48
RST: C10.2 J6.17 J6.18 J8.6 JP4.17 JP4.18 R3.2 SW1.2 U3.33 | length 2970.8
  Top Layer w8: U3.33 -1274.69,606.92 -1256.91,606.92 v2@-1177,527.01 ; J8.6 -830,-370 -585,-370 -375,-580 SW1.2 R3.2@-217.79,-479.13 ; R3.2 C10.2
  Bottom Layer w8: JP4.17 JP4.18 -1050,1150 -1050,675 -1177,548 v2(-1177,519) -1145,487 -1145,443 -1186,402 -1186,199 -1100,113 J6.18 J6.17 -1100,-50 -900,-250 J8.6
USB_BUSY: JP3.2 R2.1 U1.24 | length 692.6
  Top Layer w8: JP3.2 -245,245 76.61,245 88.82,232.8 U1.24 88.82,121.18 R2.1@205,5
USB_OK: R1.1 U1.26 | length 294
  Top Layer w8: U1.26 140,110 185,65 255,65 R1.1
VDD: C9.2 C10.1 C15.1 D3.1 D4.1 D5.1 D6.1 J2.1 J2.2 J2.3 J5.1 J5.2 J7.1 J8.3 J9.1 JP4.1 JP4.2 JP5.1 JP5.2 JP6.1 JP6.2 JP7.1 JP7.2 R4.1 R5.1 R9.2 R10.2 SW1.1 SW2.2 U3.56 | length 9951.6
  Top Layer w10: U3.56@-1373.08,308.08 -1344.17,337 v2(-1325,337)
  Top Layer w30: J5.2 -1914.91,785.09 -1914.91,700 -1914.91,590 -1914.91,430 -1914.91,276 ; v5@-1651,276 -1914.91,276 ; JP7.1 JP7.2 -1200,1075 -1140,1015 -890,1015 -805,930 -530,930 ; -745,930 -530,930 ; JP4.2 JP4.1 ; C10.1 57.79,-536.46 SW1.1 ; J7.1@400,-290 J7.1 ; SW2.2 445.04,930 290,930 195,930 105.71,930 -164.29,930 v5(-200,930) -434.29,930 -530,930 ; D3.1@511.92,-178.08 D3.1@516.92,-173.08 ; D3.1 513.84,-266.16 480,-300 J7.1 ; JP5.1 JP5.2 800,1145 855,1090 1010,1090 J2.3 J2.2 J2.1 ; -1914.91,276 -1914.91,225.09 -1960,180 -1960,-240 JP6.2 JP6.1 -1835,-465 -1735,-465 J9.1 -1531,-669 -829,-669 v2(-600,-440) -365,-675 -37.21,-675 SW1.1 ; SW1.1 235,-580 400,-415 J7.1
  Bottom Layer w15: v2@-1324,342 C9.2@-1298,342
  Bottom Layer w30: J5.2 -1800,900 -1365,900 -1200,1065 JP7.2 ; v5(-1650,275) -1595,275 ; C15.1 -1345.69,268.66 C9.2@-1287.85,326.51 ; v2(-600,-440) J8.3 ; v5(-200,930) JP4.2 ; SW2.2 584.96,984.96 JP5.2
VDD3: C8.1 J4.3 U2.1 | length 142.7
  Top Layer w30: J4.3@765,890 U2.1@810,890 ; C8.1@818.66,976.77 828.66,976.77 U2.1@828.66,889.06
VDD5: C2.2 C5.1 C7.1 D1.2 D2.1 J4.1 U1.27 U2.3 | length 1769.9
  Top Layer w13: U1.27 165.59,144.41 175,135 C2.2@295,135
  Top Layer w30: C2.2 378.66,80 v5(455,80) 513.84,21.16 D2.1 ; v5(455,335) 530,335 761.34,566.34 C7.1 ; J4.1@760,798 760,770.94 ; 775,650.63 C7.1@775,680 ; C7.1@785,679.06 C7.1@785,680 ; U2.3@841.89,770.94 U2.3 760,770.94 ; D1.2@880,559.06 C5.1@880,660 ; C5.1@880,680 C5.1 C7.1@785,680 ; 760,770.94 760,680 C7.1 ; C7.1 C7.1@775,680 ; C7.1@775,680 C7.1@785,680
  Bottom Layer w30: v5(455,80) v5(455,335)
VREF+: C16.1 J9.2 U3.57 | length 1660
  Top Layer w10: -1403,265 -1400,265 -1393.9,265 U3.57@-1375.45,283.45
  Top Layer w12: v2(-1870,185) -1845,185 -1820,210 -1617.32,210 C16.1 -1562.32,265 -1400,265
  Bottom Layer w12: v2(-1870,185) -1890,185 -1950,125 -1950,-65 -1850,-165 -1850,-430 -1730,-550 -1550,-550 J9.2
pads on no net: J1.0 J5.19 J5.20 J5.23 J5.24 J9.4 U1.6 U1.9 U1.10 U1.11 U1.12 U1.13 U1.14 U1.15 U1.16 U1.17 U1.18 U1.19 U1.20 U1.21 U1.22 U1.25

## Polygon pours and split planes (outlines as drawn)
GND_POWER on Bottom Layer "Bottom Layer-No Net" (hatched 90Degree grid 10 track 10, remove dead copper, pour order 1001): -1970,-681 1140,-681 1140,1370 -1970,1370
GND_POWER on Top Layer "Bottom Layer-No Net" (hatched 90Degree grid 10 track 10, remove dead copper, pour order 1001): -1957,-681 1140,-681 1140,1370 -1957,1370

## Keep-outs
Keep-Out Layer:
  circle w10: c1040,-595 r120
  circle w10: c-1870,1280 r120
  circle w10: c-1870,-595 r100
  circle w10: c1040,1280 r120

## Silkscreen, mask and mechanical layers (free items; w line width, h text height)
Top Overlay:
  text "P41" at -450,1105 h33
  text "P40" at -350,1105 h33
  text "VDD" at -250,1105 h33
  text "GND" at -140,1105 h33
  text "P57" at -40,1105 h33
  text "P56" at 60,1105 h33
  text "P55" at 160,1105 h33
  text "P54" at 260,1105 h33
  text "P53" at 360,1105 h33
  text "P52" at 460,1105 h33
  text "P51" at 560,1105 h33
  text "P50" at 660,1105 h33
  text "VDD" at 760,1105 h33
  text "GND" at -1585,1055 h33 r90
  text "P72" at -1485,1055 h33 r90
  text "P71" at -1390,1055 h33 r90
  text "P70" at -1285,1055 h33 r90
  text "VDD" at -1190,1055 h33 r90
  text "GND" at -1085,1055 h33 r90
  text "RST" at -985,1055 h33 r90
  text "P46" at -890,1055 h33 r90
  text "P01" at -785,1055 h33 r90
  text "P00" at -690,1055 h33 r90
  text "P43" at -580,1055 h33 r90
  text "P42" at -490,1055 h33 r90
  text "Power Off" at 415,1040 h40
  text "P46" at -855,895 h38 r90
  text "VDD3" at 598,890 h33
  text "P07" at -1080,865 h38 r90
  text "P06" at -1178,864 h38 r90
  text "P44" at -1780,862 h40 r90
  text "P45" at -1680,862 h40 r90
  text "P02" at -1579,862 h38 r90
  text "P03" at -1479,862 h38 r90
  text "P04" at -1379,862 h38 r90
  text "VDD" at -1881,861 h40 r90
  text "P05" at -1260,860 h38 r90
  text "P27" at -740,860 h35
  text "P26" at -630,860 h35
  text "P25" at -530,860 h35
  text "P24" at -430,860 h35
  text "P23" at -330,860 h35
  text "P22" at -230,860 h35
  text "P21" at -130,860 h35
  text "P20" at -30,860 h35
  text "VDD" at 625,830 h33
  text "VDD5" at 595,765 h33
  text "VDD" at 1128,610 h50 r90
  text "Power On" at 415,575 h40
  text "P31" at -430,557 h35
  text "GND" at 960,510 h33
  text "MG82FG5C64" at -1020,480 h45
  text "P30" at -466.34,350 h35 r90
  text "D+" at 640,350 h33
  text "LQFP64_V10" at -966,307.44 h45
  text "D-" at 640,305 h33
  text "Ev Board" at -966,244.45 h45
  text "P43" at -430,207 h35
  text "TH167A" at -966,179.76 h45
  text "VDD" at 960,155 h33
  text "GND" at 480,65 h33
  text "GND" at 1130,-35 h50 r90
  text "USB_Ok" at 380,-40 h38
  text "P37" at -350,-95 h35
  text "P60" at -240,-95 h35
  text "P61" at -130,-95 h35.43
  text "GND" at -30,-95 h35.43
  text "P31" at -880,-145 h40 r90
  text "RST" at -1080,-155 h40 r90
  text "P30" at -980,-155 h40 r90
  text "P32" at -778,-155 h40 r90
  text "P33" at -678,-155 h40 r90
  text "P34" at -578,-155 h40 r90
  text "P35" at -478,-155 h40 r90
  text "P36" at -378,-155 h40 r90
  text "P15" at -1386.05,-158.05 h40 r90
  text "P16" at -1286.05,-158.05 h40 r90
  text "P17" at -1186.05,-158.05 h40 r90
  text "P10" at -1880,-165 h40 r90
  text "P11" at -1790,-165 h40 r90
  text "P12" at -1690,-165 h40 r90
  text "P13" at -1580,-165 h40 r90
  text "P14" at -1480,-165 h40 r90
  text "ICE/ICP" at -785,-215 h45
  text "ISP" at 200,-220 h45
  text "VDD" at -1940,-235 h33
  text "P60" at -1840,-235 h33
  text "P61" at -1740,-235 h33
  text "P62" at -1640,-235 h33
  text "P63" at -1540,-235 h33
  text "P64" at -1440,-235 h33
  text "P65" at -1340,-235 h33
  text "P66" at -1240,-235 h33
  text "P67" at -1140,-235 h33
  text "GND" at -1040,-235 h33
  text "RST" at -930,-265 h33
  text "GND" at -835,-265 h33
  text "SDA" at -730,-265 h33
  text "VDD" at -630,-265 h33
  text "SCL" at -530,-265 h33
  text "P30" at -430,-265 h33
  text "P31" at 260,-265 h33
  text "USB_Busy" at 380,-265 h38
  text "GND" at 80,-335 h33
  text "VDD" at 440,-335 h33
  text "VREF+" at -1544,-539 h50
  text "Reset" at -155,-700 h40
Mechanical 1:
  the board outline again, w13
Mechanical 2:
  circle w10: c1040,1280 r120
  circle w10: c-1870,-595 r100
  circle w10: c-1870,1280 r120
  circle w10: c1040,-595 r120

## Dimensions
-1990,-710 to 1165,-710 on Top Overlay
-1990,1400 to -1990,-710 on Top Overlay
